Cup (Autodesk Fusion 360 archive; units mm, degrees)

design "Cup" references "Pegboard - Pegs"
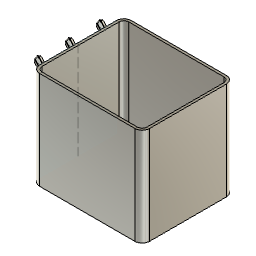
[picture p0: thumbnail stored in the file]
part number: 2025-09-18-01-06-11-150
sketch "Sketch1" plane through (0, 0, 0) normal (0, 0, 1) x axis (1, 0, 0)
  line L1 (84, 0) -> (6, 0)
  line L2 (90, 69) -> (90, 6)
  line L3 (6, 75) -> (84, 75)
  line L4 (0, 6) -> (0, 69)
  arc A1 centre (6, 6) radius 6 clockwise from (6, 0) to (0, 6)
  arc A2 centre (6, 69) radius 6 clockwise from (0, 69) to (6, 75)
  arc A3 centre (84, 69) radius 6 clockwise from (84, 75) to (90, 69)
  arc A4 centre (84, 6) radius 6 clockwise from (90, 6) to (84, 0)
  point P1 (0, 0)
  point P2 (0, 0)
  point P4 (0, 75)
  point P3 (90, 0)
  horizontal L1
  vertical L2
  horizontal L3
  vertical L4
  coincident P1 P2
  coincident P2 L1
  coincident P2 L4
  tangent L1 A1
  tangent L4 A1
  coincident P4 L3
  coincident P4 L4
  tangent L3 A2
  tangent L4 A2
  tangent L2 A3
  tangent L3 A3
  equal A2 A3
  coincident P3 L2
  coincident P3 L1
  tangent L2 A4
  tangent L1 A4
  equal A2 A4
  dimension "d1" distance P2 P3 = 90
  dimension "d2" distance P2 P4 = 75
  dimension "d3" radius A1 = 6
  dimension "d4" radius A2 = 6
extrude "Extrude1" new body sketch "Sketch1" along normal blind 80
shell "Shell1" innerThickness 2
external_derived "ExternalDerived1"
move "Move1"
copy_paste_bodies "CopyPasteBodies1"
move "Move2" TranslateX 0 TranslateY -25.4 TranslateZ 0
copy_paste_bodies "CopyPasteBodies2"
move "Move3" TranslateX 0 TranslateY -25.4 TranslateZ 0
sketch "Sketch4" plane through (0, 0, 0) normal (-1, 0, 0) x axis (0, -1, 0)
  line L1 (-6, 0) -> (-69, 0)
  line L2 (-6, 80) -> (-6, 0)
  line L3 (-69, 80) -> (-6, 80)
  line L4 (-69, 0) -> (-69, 80)
  line L5 (-37.5, 0) -> (-37.5, 80)
  point P6 (-37.5, 80)
  point P7 (-37.5, 0)
  midpoint L3 P6
  midpoint L1 P7
move "Move4" TranslateX 0 TranslateY -3 TranslateZ 5
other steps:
derived_base_feature "Derived Base Feature"
base_feature "Base Feature1" bodies "Body21", "Body13", "Body12", "Body21 (1)", "Body13 (1)", "Body12 (1)"
base_feature "Base Feature2" bodies "Body13 (1)", "Body21 (1)", "Body12 (1)", "Body13 (1) (1)", "Body21 (1) (1)", "Body12 (1) (1)"
named bodies: "Body21", "Body13", "Body12", "Body21 (1)", "Body13 (1)", "Body12 (1)", "Body13 (1) (1)", "Body21 (1) (1)", "Body12 (1) (1)"

design "Pegboard - Pegs"
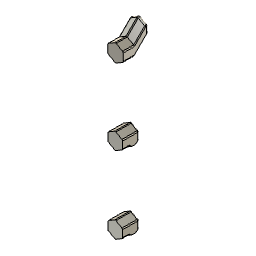
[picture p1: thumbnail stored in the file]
description: STEP AP203
part number: pegboard locking pins
copy_paste_bodies "CopyPasteBodies7"
move "Move15"
scale "Scale1" ScaleFactor 0.95
scale "Scale2" ScaleFactor 0.95
move "Move20" TranslateX 0 TranslateY 0 TranslateZ 0.3556
copy_paste_bodies "CopyPasteBodies11"
move "Move21" TranslateX 0 TranslateY 0 TranslateZ -25.4
sketch "Sketch3" plane through (0, 0, 0) normal (1, 0, 0) x axis (0, 1, 0)
move "Move22" TranslateX 0 TranslateY -1.27 TranslateZ 0
move "Move23" TranslateX 0 TranslateY -0.254 TranslateZ 0
move "Move24" TranslateX 0 TranslateY -0.254 TranslateZ 0
move "Move25" TranslateX 0 TranslateY 68.58 TranslateZ 0
move "Move26" TranslateX 0 TranslateY -0.1778 TranslateZ 0
move "Move27" TranslateX 0 TranslateY -0.1143 TranslateZ 0
move "Move28" TranslateX 0 TranslateY -0.1194 TranslateZ 0
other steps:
base_feature "Base Feature8" TranslateX 25.4 TranslateY 0 TranslateZ 0 distance 1
base_feature "Base Feature12"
